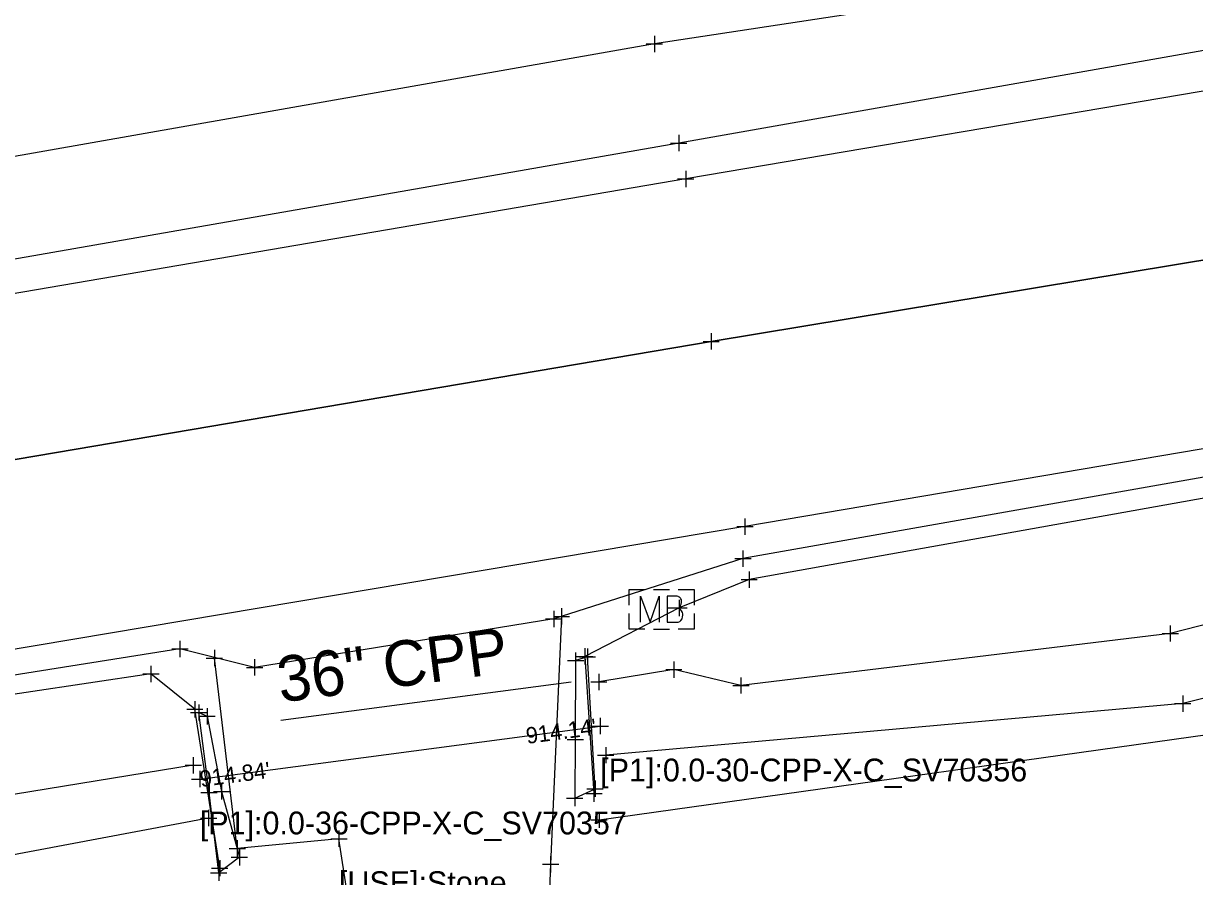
# Model space of a CAD drawing. Extents: x 1386013 to 1389776, y 604170 to 607009.
# Drawn here: x 1387085.1 to 1387157, y 604729.1 to 604781.5 of the extents above; entities that cross this region are included whole.
import ezdxf

# ---------------------------------------------------------------- set-up
doc = ezdxf.new("R2010")
doc.units = 0
for name, color, linetype in [('DR_X_Headwall', 7, 'Continuous'), ('DR_X_Storm_Sewer', 7, 'Continuous'), ('DR_X_Text', 7, 'Continuous'), ('DV_X_Text', 7, 'Continuous'), ('PM_X_CL_Double_Solid', 7, 'Continuous'), ('PV_X_COP', 7, 'Continuous'), ('PV_X_Driveway', 7, 'Continuous'), ('PV_X_EOP', 7, 'Continuous'), ('PV_X_Shoulder', 7, 'Continuous'), ('RD_X_Cells', 7, 'Continuous'), ('SC_Scratch1', 7, 'Continuous'), ('SV_X_Text', 7, 'Continuous'), ('SV_X_Toe_of_Slope', 7, 'Continuous'), ('SV_X_Top_of_Bank', 7, 'Continuous')]:
    doc.layers.add(name, color=color, linetype=linetype)

msp = doc.modelspace()

# ---------------------------------------------------------------- linework, layer by layer
at = {"layer": 'DR_X_Headwall'}
for points in [[(1387118.946, 604733.89), (1387120.194, 604734.464), (1387119.728, 604742.57), (1387118.998, 604742.335), (1387118.978, 604737.48)], [(1387098.35, 604730.262), (1387097.079, 604729.309), (1387096.487, 604734.229), (1387095.854, 604739.146), (1387096.364, 604738.917), (1387097.255, 604734.302)]]:
    msp.add_lwpolyline(points, close=True, dxfattribs=at)
at = {"layer": 'DR_X_Storm_Sewer'}
msp.add_line((1387095.919, 604735.064), (1387120.509, 604738.316), dxfattribs=at)
at = {"layer": 'DR_X_Text'}
msp.add_line((1387118.731, 604741.006), (1387100.902, 604738.648), dxfattribs=at)
at = {"layer": 'DV_X_Text'}
for p, q in [((1387123.339, 604780.194), (1387124.339, 604780.194)), ((1387123.839, 604780.694), (1387123.839, 604779.694)), ((1387123.839, 604780.194), (1387123.839, 604780.194)), ((1387125.331, 604774.604), (1387125.331, 604773.604)), ((1387124.831, 604774.104), (1387125.831, 604774.104)), ((1387125.331, 604774.104), (1387125.331, 604774.104)), ((1387125.76, 604772.411), (1387125.76, 604771.411)), ((1387125.26, 604771.911), (1387126.26, 604771.911)), ((1387125.76, 604771.911), (1387125.76, 604771.911)), ((1387127.324, 604762.435), (1387127.324, 604761.435)), ((1387126.824, 604761.935), (1387127.824, 604761.935)), ((1387127.324, 604761.935), (1387127.324, 604761.935)), ((1387129.398, 604751.063), (1387129.398, 604750.063)), ((1387128.898, 604750.563), (1387129.898, 604750.563)), ((1387129.398, 604750.563), (1387129.398, 604750.563)), ((1387128.778, 604748.594), (1387129.778, 604748.594)), ((1387129.278, 604749.094), (1387129.278, 604748.094)), ((1387129.278, 604748.594), (1387129.278, 604748.594)), ((1387129.658, 604747.804), (1387129.658, 604746.804)), ((1387129.158, 604747.304), (1387130.158, 604747.304)), ((1387129.658, 604747.304), (1387129.658, 604747.304)), ((1387125.36, 604746.067), (1387125.36, 604745.067)), ((1387117.634, 604745.046), (1387118.634, 604745.046)), ((1387117.652, 604745.392), (1387117.652, 604744.392)), ((1387118.134, 604745.546), (1387118.134, 604744.546)), ((1387118.134, 604745.046), (1387118.134, 604745.046)), ((1387124.86, 604745.567), (1387125.86, 604745.567)), ((1387125.36, 604745.567), (1387125.36, 604745.567)), ((1387117.152, 604744.892), (1387118.152, 604744.892)), ((1387117.652, 604744.892), (1387117.652, 604744.892)), ((1387155.521, 604744.497), (1387155.521, 604743.497)), ((1387094.703, 604743.554), (1387094.703, 604742.554)), ((1387155.021, 604743.997), (1387156.021, 604743.997)), ((1387155.521, 604743.997), (1387155.521, 604743.997)), ((1387094.203, 604743.054), (1387095.203, 604743.054)), ((1387094.703, 604743.054), (1387094.703, 604743.054)), ((1387096.815, 604742.993), (1387096.815, 604741.993)), ((1387118.998, 604742.835), (1387118.998, 604741.835)), ((1387119.562, 604743.091), (1387119.562, 604742.091)), ((1387119.728, 604743.07), (1387119.728, 604742.07)), ((1387096.315, 604742.493), (1387097.315, 604742.493)), ((1387096.815, 604742.493), (1387096.815, 604742.493)), ((1387099.288, 604742.413), (1387099.288, 604741.413)), ((1387118.498, 604742.335), (1387119.498, 604742.335)), ((1387118.998, 604742.335), (1387118.998, 604742.335)), ((1387119.062, 604742.591), (1387120.062, 604742.591)), ((1387119.228, 604742.57), (1387120.228, 604742.57)), ((1387119.562, 604742.591), (1387119.562, 604742.591)), ((1387119.728, 604742.57), (1387119.728, 604742.57)), ((1387125.031, 604742.281), (1387125.031, 604741.281)), ((1387092.422, 604741.518), (1387093.422, 604741.518)), ((1387092.922, 604742.018), (1387092.922, 604741.018)), ((1387092.922, 604741.518), (1387092.922, 604741.518)), ((1387098.788, 604741.913), (1387099.788, 604741.913)), ((1387099.288, 604741.913), (1387099.288, 604741.913)), ((1387120.426, 604741.523), (1387120.426, 604740.523)), ((1387124.531, 604741.781), (1387125.531, 604741.781)), ((1387125.031, 604741.781), (1387125.031, 604741.781)), ((1387119.926, 604741.023), (1387120.926, 604741.023)), ((1387120.426, 604741.023), (1387120.426, 604741.023)), ((1387128.65, 604740.805), (1387129.65, 604740.805)), ((1387129.15, 604741.305), (1387129.15, 604740.305)), ((1387129.15, 604740.805), (1387129.15, 604740.805)), ((1387156.282, 604740.191), (1387156.282, 604739.191)), ((1387095.116, 604739.344), (1387096.116, 604739.344)), ((1387095.616, 604739.844), (1387095.616, 604738.844)), ((1387095.616, 604739.344), (1387095.616, 604739.344)), ((1387095.854, 604739.646), (1387095.854, 604738.646)), ((1387096.364, 604739.417), (1387096.364, 604738.417)), ((1387155.782, 604739.691), (1387156.782, 604739.691)), ((1387156.282, 604739.691), (1387156.282, 604739.691)), ((1387095.354, 604739.146), (1387096.354, 604739.146)), ((1387095.854, 604739.146), (1387095.854, 604739.146)), ((1387095.864, 604738.917), (1387096.864, 604738.917)), ((1387096.364, 604738.917), (1387096.364, 604738.917)), ((1387120.509, 604738.816), (1387120.509, 604737.816)), ((1387118.978, 604737.98), (1387118.978, 604736.98)), ((1387120.009, 604738.316), (1387121.009, 604738.316)), ((1387120.509, 604738.316), (1387120.509, 604738.316)), ((1387118.478, 604737.48), (1387119.478, 604737.48)), ((1387118.978, 604737.48), (1387118.978, 604737.48)), ((1387120.849, 604737.029), (1387120.849, 604736.029)), ((1387095.517, 604736.405), (1387095.517, 604735.405)), ((1387120.349, 604736.529), (1387121.349, 604736.529)), ((1387120.849, 604736.529), (1387120.849, 604736.529)), ((1387095.017, 604735.905), (1387096.017, 604735.905)), ((1387095.517, 604735.905), (1387095.517, 604735.905)), ((1387095.919, 604735.564), (1387095.919, 604734.564)), ((1387095.419, 604735.064), (1387096.419, 604735.064)), ((1387095.919, 604735.064), (1387095.919, 604735.064)), ((1387120.194, 604734.964), (1387120.194, 604733.964)), ((1387095.987, 604734.229), (1387096.987, 604734.229)), ((1387096.487, 604734.729), (1387096.487, 604733.729)), ((1387096.487, 604734.229), (1387096.487, 604734.229)), ((1387096.755, 604734.302), (1387097.755, 604734.302)), ((1387097.255, 604734.802), (1387097.255, 604733.802)), ((1387097.255, 604734.302), (1387097.255, 604734.302)), ((1387118.946, 604734.39), (1387118.946, 604733.39)), ((1387119.62, 604734.169), (1387120.62, 604734.169)), ((1387119.694, 604734.464), (1387120.694, 604734.464)), ((1387120.12, 604734.669), (1387120.12, 604733.669)), ((1387120.12, 604734.169), (1387120.12, 604734.169)), ((1387120.194, 604734.464), (1387120.194, 604734.464)), ((1387118.446, 604733.89), (1387119.446, 604733.89)), ((1387118.946, 604733.89), (1387118.946, 604733.89)), ((1387096.459, 604733.168), (1387096.459, 604732.168)), ((1387120.443, 604733.058), (1387120.443, 604732.058)), ((1387095.959, 604732.668), (1387096.959, 604732.668)), ((1387096.459, 604732.668), (1387096.459, 604732.668)), ((1387119.943, 604732.558), (1387120.943, 604732.558)), ((1387120.443, 604732.558), (1387120.443, 604732.558)), ((1387098.218, 604731.305), (1387098.218, 604730.305)), ((1387103.964, 604731.399), (1387104.964, 604731.399)), ((1387104.464, 604731.899), (1387104.464, 604730.899)), ((1387104.464, 604731.399), (1387104.464, 604731.399)), ((1387097.718, 604730.805), (1387098.718, 604730.805)), ((1387098.218, 604730.805), (1387098.218, 604730.805)), ((1387098.35, 604730.762), (1387098.35, 604729.762)), ((1387097.079, 604729.809), (1387097.079, 604728.809)), ((1387097.142, 604730.09), (1387097.142, 604729.09)), ((1387097.85, 604730.262), (1387098.85, 604730.262)), ((1387098.35, 604730.262), (1387098.35, 604730.262)), ((1387116.963, 604729.829), (1387117.963, 604729.829)), ((1387117.463, 604730.329), (1387117.463, 604729.329)), ((1387117.463, 604729.829), (1387117.463, 604729.829)), ((1387096.579, 604729.309), (1387097.579, 604729.309)), ((1387096.642, 604729.59), (1387097.642, 604729.59)), ((1387097.079, 604729.309), (1387097.079, 604729.309)), ((1387097.142, 604729.59), (1387097.142, 604729.59))]:
    msp.add_line(p, q, dxfattribs=at)
at = {"layer": 'PM_X_CL_Double_Solid'}
msp.add_lwpolyline([(1386941.923, 604730.568), (1387000.365, 604739.899), (1387059.378, 604750.405), (1387127.324, 604761.935), (1387175.516, 604769.899), (1387233.308, 604779.132), (1387291.846, 604789.882), (1387343.041, 604798.389), (1387403.896, 604809.054), (1387458.493, 604818.933), (1387516.124, 604829.584), (1387574.819, 604839.732), (1387636.991, 604851.11), (1387704.346, 604863.012), (1387787.502, 604877.74), (1387859.733, 604890.761), (1387934.468, 604903.864), (1387998.852, 604914.969), (1388072.268, 604927.437)], dxfattribs=at)
at = {"layer": 'PV_X_COP'}
msp.add_lwpolyline([(1388072.268, 604927.437), (1387998.852, 604914.969), (1387934.468, 604903.864), (1387859.733, 604890.761), (1387787.502, 604877.74), (1387704.346, 604863.012), (1387636.991, 604851.11), (1387574.819, 604839.732), (1387516.124, 604829.584), (1387458.493, 604818.933), (1387403.896, 604809.054), (1387343.041, 604798.389), (1387291.846, 604789.882), (1387233.308, 604779.132), (1387175.516, 604769.899), (1387127.324, 604761.935), (1387059.378, 604750.405), (1387000.365, 604739.899), (1386941.923, 604730.568)], dxfattribs=at)
at = {"layer": 'PV_X_Driveway'}
msp.add_lwpolyline([(1387118.134, 604745.046), (1387117.463, 604729.829), (1387116.741, 604711.351), (1387120.406, 604675.776), (1387122.468, 604635.8), (1387113.896, 604634.772), (1387110.678, 604673.979), (1387107.501, 604711.745), (1387104.464, 604731.399), (1387098.218, 604730.805), (1387096.815, 604742.493)], dxfattribs=at)
at = {"layer": 'PV_X_EOP'}
for points in [[(1388070.904, 604937.92), (1387997.667, 604925.455), (1387932.448, 604914.147), (1387857.846, 604900.917), (1387785.098, 604888.089), (1387704.04, 604873.647), (1387634.939, 604861.367), (1387573.227, 604850.33), (1387514.484, 604840.103), (1387457.169, 604829.653), (1387402.439, 604819.904), (1387341.383, 604808.9), (1387290.361, 604800.04), (1387231.983, 604789.906), (1387174.346, 604780.147), (1387125.76, 604771.911), (1387057.817, 604760.304), (1386999.091, 604750.972), (1386941.405, 604741.044)], [(1388073.477, 604916.736), (1388000.199, 604904.184), (1387936.608, 604893.172), (1387860.997, 604879.892), (1387788.154, 604866.907), (1387706.182, 604852.378), (1387637.623, 604840.161), (1387577.036, 604829.262), (1387518.08, 604818.578), (1387459.961, 604808.241), (1387405.362, 604798.504), (1387345.113, 604787.749), (1387291.8, 604778.426), (1387234.86, 604768.47), (1387177.431, 604758.697), (1387129.398, 604750.563), (1387061.715, 604739.203), (1387002.895, 604729.166), (1386943.417, 604719.405)]]:
    msp.add_lwpolyline(points, dxfattribs=at)
at = {"layer": 'PV_X_Shoulder'}
for points in [[(1388070.878, 604939.746), (1387997.08, 604927.243), (1387932.098, 604916.229), (1387857.343, 604902.988), (1387785.161, 604890.04), (1387703.388, 604875.425), (1387634.349, 604863.658), (1387572.417, 604852.644), (1387514.095, 604842.112), (1387456.78, 604832.264), (1387401.906, 604822.43), (1387340.627, 604811.343), (1387290.105, 604802.669), (1387231.448, 604791.93), (1387174.182, 604782.714), (1387125.331, 604774.104), (1387057.538, 604762.256), (1386998.586, 604752.703), (1386940.974, 604743.321)], [(1388073.661, 604915.378), (1388000.633, 604902.689), (1387936.793, 604891.841), (1387860.981, 604878.417), (1387788.185, 604865.058), (1387706.381, 604850.403), (1387637.881, 604838.495), (1387577.023, 604827.533), (1387518.116, 604817.165), (1387460.261, 604806.851), (1387405.505, 604796.968), (1387345.324, 604786.502), (1387292.135, 604776.932), (1387235.042, 604767.03), (1387177.496, 604757.127), (1387129.278, 604748.594), (1387117.652, 604744.892), (1387099.288, 604741.913), (1387094.703, 604743.054), (1387062.03, 604737.865), (1387002.752, 604727.469), (1386990.609, 604725.246), (1386985.404, 604722.838), (1386965.111, 604719.464)]]:
    msp.add_lwpolyline(points, dxfattribs=at)
at = {"layer": 'RD_X_Cells'}
for p, q in [((1387123.773, 604746.708), (1387124.775, 604746.708)), ((1387124.285, 604745.487), (1387124.285, 604745.487)), ((1387123.773, 604744.265), (1387124.775, 604744.265))]:
    msp.add_line(p, q, dxfattribs=at)
for points in [[(1387122.285, 604745.738), (1387122.285, 604746.708), (1387123.255, 604746.708)], [(1387125.292, 604746.708), (1387126.285, 604746.708), (1387126.285, 604745.738)], [(1387122.989, 604744.687), (1387122.989, 604746.287), (1387123.568, 604744.687), (1387124.122, 604746.287), (1387124.122, 604744.687)], [(1387125.307, 604745.556), (1387125.37, 604745.619), (1387125.408, 604745.657), (1387125.433, 604745.694), (1387125.445, 604745.72), (1387125.47, 604745.77), (1387125.483, 604745.808), (1387125.508, 604745.896), (1387125.508, 604745.934), (1387125.508, 604745.984), (1387125.496, 604746.06), (1387125.47, 604746.123), (1387125.433, 604746.173), (1387125.37, 604746.223), (1387125.319, 604746.249), (1387125.294, 604746.261), (1387125.231, 604746.287), (1387124.614, 604746.287), (1387124.614, 604744.687), (1387125.307, 604744.687), (1387125.395, 604744.737), (1387125.47, 604744.8), (1387125.533, 604744.901), (1387125.571, 604745.014), (1387125.584, 604745.128), (1387125.584, 604745.203), (1387125.559, 604745.279), (1387125.508, 604745.392), (1387125.445, 604745.468), (1387125.307, 604745.556), (1387124.614, 604745.556)], [(1387123.255, 604744.265), (1387122.285, 604744.265), (1387122.285, 604745.235)], [(1387126.285, 604745.235), (1387126.285, 604744.265), (1387125.292, 604744.265)]]:
    msp.add_lwpolyline(points, dxfattribs=at)
at = {"layer": 'SV_X_Toe_of_Slope'}
for points in [[(1387571.903, 604860.127), (1387513.167, 604847.9), (1387455.733, 604837.689), (1387401.036, 604827.645), (1387339.29, 604815.833), (1387289.098, 604807.737), (1387230.034, 604798.146), (1387173.084, 604787.711), (1387123.839, 604780.194), (1387058.581, 604768.724), (1386997.091, 604757.108), (1386939.93, 604748.726), (1386883.975, 604739.003), (1386826.094, 604728.816), (1386769.039, 604719.027), (1386711.703, 604710.765), (1386654.026, 604700.724), (1386592.595, 604690.633), (1386534.099, 604681.178), (1386480.031, 604672.894), (1386465.511, 604671.66), (1386391.458, 604656.555), (1386330.799, 604647.358), (1386266.182, 604637.162)], [(1387642.644, 604832.214), (1387598.475, 604823.295), (1387558.951, 604817.367), (1387510.991, 604808.944), (1387471.623, 604802.749), (1387417.674, 604793.627), (1387365.328, 604784.072), (1387322.852, 604775.638), (1387270.329, 604764.795), (1387223.528, 604756.91), (1387181.6, 604750.673), (1387155.521, 604743.997), (1387129.15, 604740.805), (1387125.031, 604741.781), (1387120.426, 604741.023)], [(1387645.487, 604830.059), (1387640.632, 604828.806), (1387599.431, 604819.649), (1387560.444, 604813.109), (1387511.639, 604804.792), (1387472.902, 604799.006), (1387418.895, 604788.909), (1387366.412, 604779.888), (1387324.468, 604770.631), (1387271.89, 604759.841), (1387225.55, 604751.965), (1387182.661, 604746.288), (1387156.282, 604739.691), (1387120.849, 604736.529)], [(1387095.517, 604735.905), (1387051.848, 604728.784), (1387018.465, 604723.844), (1387000.988, 604719.534), (1386993.696, 604717.562)], [(1387096.459, 604732.668), (1387053.45, 604724.567), (1387019.694, 604718.705), (1387001.856, 604714.125), (1386994.321, 604715.105)]]:
    msp.add_lwpolyline(points, dxfattribs=at)
at = {"layer": 'SV_X_Top_of_Bank'}
for points in [[(1387579.309, 604826.78), (1387518.181, 604816.157), (1387495.205, 604811.897), (1387460.53, 604806.404), (1387405.654, 604795.747), (1387345.732, 604785.646), (1387292.402, 604775.678), (1387235, 604765.96), (1387177.615, 604755.882), (1387129.658, 604747.304), (1387125.36, 604745.567), (1387119.562, 604742.591), (1387120.12, 604734.169)], [(1387120.443, 604732.558), (1387162.467, 604738.459), (1387215.738, 604745.531), (1387273.799, 604754.329), (1387315.903, 604762.485), (1387378.293, 604774.446), (1387445.093, 604787.578), (1387492.001, 604798.409), (1387538.689, 604807.909), (1387587.499, 604815.895), (1387625.324, 604823.628), (1387642.483, 604825.613)], [(1387097.142, 604729.59), (1387095.616, 604739.344), (1387092.922, 604741.518), (1387062.273, 604736.945), (1387002.994, 604726.32), (1386994.076, 604724.574), (1386989.998, 604719.259), (1386990.774, 604712.025)]]:
    msp.add_lwpolyline(points, dxfattribs=at)

# ---------------------------------------------------------------- texts
at = {"layer": 'DR_X_Text'}
msp.add_text('36" CPP', height=2.8, rotation=7.53221, dxfattribs=at).set_placement((1387100.871, 604739.756))
at = {"layer": 'SC_Scratch1'}
for s, p in [("914.14'", (1387116.016, 604737.217)), ("914.84'", (1387095.985, 604734.569))]:
    msp.add_text(s, height=1, rotation=7.53221, dxfattribs=at).set_placement(p)
at = {"layer": 'SV_X_Text'}
for s, p in [('[P1]:0.0-30-CPP-X-C_SV70356', (1387120.509, 604734.916)), ('[P1]:0.0-36-CPP-X-C_SV70357', (1387095.919, 604731.664)), ('[USE]:Stone', (1387104.464, 604727.999))]:
    msp.add_text(s, height=1.4, dxfattribs=at).set_placement(p)

doc.saveas('drawing.dxf')
